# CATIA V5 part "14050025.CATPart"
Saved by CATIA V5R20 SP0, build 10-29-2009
Part number: 14050025
Definition: NONE
Nomenclature: 14050025
Source: Unknown
Description: 14050025
Bounding box of the stored display mesh (mm): x -12.5 to 50, y -39 to 29.1, z -29.1 to 29.1
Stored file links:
  C:\Users\Utente\Desktop\IO LAVORO\3D X SITO CF\X SITO\PLASTICA\RF2\14050025.CATPart
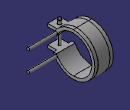
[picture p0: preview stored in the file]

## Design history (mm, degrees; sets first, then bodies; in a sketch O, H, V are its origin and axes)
Body1 "14050025" (main body)
  Solid1: solid without history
